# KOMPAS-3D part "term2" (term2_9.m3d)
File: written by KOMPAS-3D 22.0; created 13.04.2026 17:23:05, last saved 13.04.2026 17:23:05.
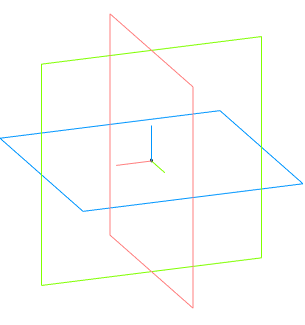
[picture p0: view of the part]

Document properties: Автор: Andrey; Полное имя файла: C:\Users\User1\Documents\term2_9.m3d

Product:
- Part/product: term2

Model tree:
1. Операция без истории:1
